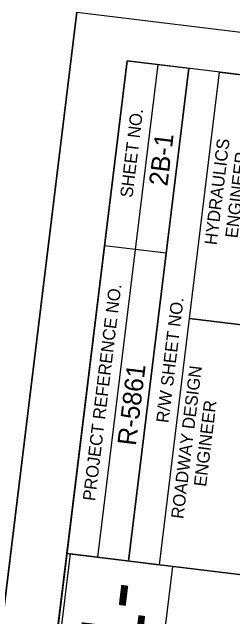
# Model space of a CAD drawing. Extents: x 480344 to 482186, y 488805 to 491553.
# Drawn here: x 480793.8 to 480882.7, y 490365.2 to 490608.9 of the extents above; entities that cross this region are included whole.
import ezdxf

# ---------------------------------------------------------------- set-up
doc = ezdxf.new("R2010")
doc.units = 0
for name, color, linetype in [('Old_Level_1', 7, 'Continuous'), ('Prop Grid Mask', 7, 'Continuous'), ('Sheet Cutting Line CELL', 7, 'Continuous'), ('Sheet Data Field CELL', 7, 'Continuous'), ('Sheet Layout Plan Border', 7, 'Continuous'), ('Sheet Plan CELL', 7, 'Continuous'), ('Sheet Plot Border Inside CELL', 7, 'Continuous'), ('Sheet Plot Border Outside CELL', 7, 'Continuous')]:
    doc.layers.add(name, color=color, linetype=linetype)

msp = doc.modelspace()

# ---------------------------------------------------------------- linework, layer by layer
at = {"layer": 'Prop Grid Mask'}
msp.add_lwpolyline([(480817.17, 490390.57), (480798.09, 490234.37), (480839.49, 490229.31), (480858.56, 490385.52)], close=True, dxfattribs=at)
at = {"layer": 'Sheet Cutting Line CELL'}
msp.add_line((480819.86, 490608.9), (480615.75, 488937.82), dxfattribs=at)
at = {"layer": 'Sheet Layout Plan Border'}
msp.add_lwpolyline([(481703.23, 488995.25), (481861.69, 490292.69), (481782.27, 490302.39), (481802.94, 490471.69), (481574.79, 490460.72), (481089.79, 490519.96), (481007.71, 490529.98), (480988.13, 490369.7), (480815.85, 490390.73), (480660.97, 489122.55)], close=True, dxfattribs=at)
at = {"layer": 'Sheet Plan CELL'}
for p, q in [((480828.31, 490389.2), (480852.57, 490587.77)), ((480840.75, 490387.69), (480864.98, 490586.25)), ((480840.75, 490387.69), (480864.98, 490586.25)), ((480831.08, 490514.81), (480855.9, 490511.83)), ((480865.28, 490485.49), (480976.91, 490471.86)), ((480658.28, 489100.33), (480815.85, 490390.73)), ((480815.85, 490390.73), (480964.81, 490372.55)), ((480840.39, 490387.74), (480852.78, 490386.22))]:
    msp.add_line(p, q, dxfattribs=at)
for points in [[(480840.12, 490589.33), (480658.26, 489100.35), (481700.51, 488973.06), (481882.37, 490462)], [(480815.85, 490390.73), (480840.12, 490589.33), (480864.98, 490586.25), (480840.75, 490387.69)], [(480865.28, 490485.49), (480877.39, 490584.74), (480989.07, 490571.11), (480976.96, 490471.85)], [(480853.15, 490386.17), (480865.28, 490485.49), (480976.96, 490471.85), (480964.81, 490372.55)]]:
    msp.add_lwpolyline(points, close=True, dxfattribs=at)
at = {"layer": 'Sheet Plot Border Inside CELL'}
msp.add_lwpolyline([(481705.46, 488972.43), (481887.32, 490461.41), (480840.14, 490589.31), (480658.28, 489100.33)], close=True, dxfattribs=at)
at = {"layer": 'Sheet Plot Border Outside CELL'}
msp.add_lwpolyline([(480615.75, 488937.82), (480819.86, 490608.9), (481906.78, 490476.15), (481702.68, 488805.07)], close=True, dxfattribs=at)

# ---------------------------------------------------------------- texts
at = {"layer": 'Old_Level_1'}
msp.add_text('-L_DET1-', height=25, rotation=83.0365, dxfattribs=at).set_placement((480831.37, 490234.39))
at = {"layer": 'Sheet Data Field CELL'}
for s, p in [('2B-1', (480856.33, 490538.54)), ('R-5861', (480843.62, 490433.94))]:
    msp.add_text(s, height=7.5, rotation=83.0365, dxfattribs=at).set_placement(p)
at = {"layer": 'Sheet Plan CELL'}
for s, height, p in [('SHEET NO.', 5, (480842.25, 490533.95)), ('HYDRAULICS', 5, (480876.19, 490514.84)), ('ENGINEER', 5, (480884.55, 490517.61)), ('PROJECT REFERENCE NO.', 5.0001, (480827.2, 490411.71)), ('R/W SHEET NO.', 5.0001, (480856.78, 490443.15)), ('ROADWAY DESIGN', 5.0001, (480862.74, 490404.52)), ('ENGINEER', 5, (480871.92, 490417.49))]:
    msp.add_text(s, height=height, rotation=83.0365, dxfattribs=at).set_placement(p)

doc.saveas('drawing.dxf')
